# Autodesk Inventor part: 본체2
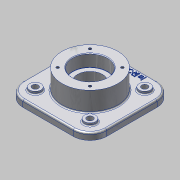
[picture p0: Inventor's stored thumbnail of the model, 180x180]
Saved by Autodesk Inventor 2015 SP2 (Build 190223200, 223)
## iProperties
Created: 2015-07
Part Number: 본체2
Material: 알루미늄 6061
Document SubType Name: Modeling
Designer: AMC
Density: 2.7 g/cm^3
Appearance: 알루미늄 - 평지
Mass: 1457.56 g
Surface Area: 803.25 cm^2
Volume: 539.836 cm^3
Author: AMC
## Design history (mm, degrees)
sketch "스케치1"
  geometry: L1 (-75, -75)-(75, -75); L2 (75, -75)-(75, 75); L3 (75, 75)-(-75, 75); L4 (-75, 75)-(-75, -75); L5 (-75, -75)-(75, 75); L6 (75, -75)-(-75, 75); 1 further point
  constraints: 12 end point, 2 midpoint, 2 parallel, 1 horizontal, 1 perpendicular
  dimensions: "d0" = 150 distance of L3.end L2.end; "d1" = 150 distance of L2.end L1.end
extrude "돌출1" new body sketch "스케치1" distance "d2" = 12; taper "d3" = 0 deg
sketch "스케치2"
  geometry: C1 r 50 at (0, 0); 1 further point
  constraints: 1 centre point, 1 coincident
  dimensions: "d4" = 100 diameter of C1
extrude "돌출2" join sketch "스케치2" stored distance "d5" = 70; taper "d6" = 0 deg
hole "구멍1" diameter "d9" = 45; stored, may be unused: countersink angle "d13" = 90 deg, drill point angle "d15" = 0 deg; dims "d10" = 6, "d11" = 62, "d12" = 22, "d14" = 35, "d132" = 10, "d133" = 10
hole "구멍2" diameter "d18" = 45; stored, may be unused: countersink angle "d22" = 90 deg, drill point angle "d24" = 0 deg; dims "d19" = 6, "d20" = 62, "d21" = 22, "d23" = 35, "d134" = 10, "d135" = 10
sketch "스케치3"
  geometry: L1 (0, 0)-(41, 0); L2 (0, 0)-(28.991, -28.991); A1 r 41 centre (0, 0) between (41, 0) and (28.991, -28.991); 1 further point
  constraints: 4 end point, 2 point on circle, 1 centre point, 1 coincident, 1 horizontal
  dimensions: "d25" = 82 diameter of A1; "d26" = 45 deg angle of L2 L1
hole "구멍3" sketch "스케치3" at (28.991, -28.991) diameter "d27" = 4.917; stored, may be unused: countersink angle "d31" = 90 deg, drill point angle "d33" = 118 deg; dims "d28" = 10, "d29" = 52, "d30" = 22, "d32" = 13
sketch "스케치4"
  geometry: L1 (0, 0)-(41, 0); L2 (0, 0)-(28.991, -28.991); A1 r 41 centre (0, 0) between (41, 0) and (28.991, -28.991); 1 further point
  constraints: 4 end point, 2 point on circle, 1 centre point, 1 coincident, 1 horizontal
  dimensions: "d37" = 82 diameter of A1; "d38" = 45 deg angle of L2 L1
hole "구멍4" sketch "스케치4" at (28.991, -28.991) diameter "d39" = 4.917; stored, may be unused: countersink angle "d43" = 90 deg, drill point angle "d45" = 118 deg; dims "d40" = 10, "d41" = 52, "d42" = 22, "d44" = 13
sketch "스케치6"
  geometry: L1 (75, 75)-(-75, 75) reference; L2 (-75, 75)-(-75, -75) reference; L3 (-75, -75)-(75, -75) reference; L4 (75, -75)-(75, 75) reference; C1 r 10 at (-49, 49); C2 r 10 at (49, 49); C3 r 10 at (49, -49); C4 r 10 at (-49, -49); 1 further point
  constraints: 4 centre point
  dimensions: "d72" = 20 diameter of C1; "d73" = 20 diameter of C2; "d74" = 20 diameter of C3; "d75" = 20 diameter of C4; "d76" = 26 distance from line of C1.centre L1; "d77" = 26 distance from line of L2 C1.centre; "d78" = 26 distance from line of C4.centre L2; "d79" = 26 distance from line of L3 C4.centre; "d80" = 26 distance from line of L4 C3.centre; "d81" = 26 distance from line of L3 C3.centre; "d82" = 26 distance from line of C2.centre L1; "d83" = 26 distance from line of C2.centre L4
extrude "돌출4" join sketch "스케치6" distance "d84" = 5; taper "d85" = 0 deg
hole "구멍6" diameter "d88" = 11; stored, may be unused: countersink angle "d92" = 90 deg, drill point angle "d94" = 0 deg; dims "d86" = 10, "d87" = 10, "d89" = 10, "d90" = 52, "d91" = 22, "d93" = 50
hole "구멍7" diameter "d97" = 11; stored, may be unused: countersink angle "d101" = 90 deg, drill point angle "d103" = 0 deg; dims "d95" = 10, "d96" = 10, "d98" = 10, "d99" = 52, "d100" = 22, "d102" = 50
hole "구멍8" diameter "d106" = 11; stored, may be unused: countersink angle "d110" = 90 deg, drill point angle "d112" = 0 deg; dims "d104" = 10, "d105" = 10, "d107" = 10, "d108" = 52, "d109" = 22, "d111" = 50
hole "구멍9" diameter "d115" = 11; stored, may be unused: countersink angle "d119" = 90 deg, drill point angle "d121" = 0 deg; dims "d113" = 10, "d114" = 10, "d116" = 10, "d117" = 52, "d118" = 22, "d120" = 50
fillet "모깎기1" dims "d122" = 2
fillet "모깎기2" dims "d123" = 30
fillet "모깎기4" dims "d125" = 0.3
chamfer "모따기1" distance "d126" = 1; stored, may be unused: second distance "d127" = 2, angle "d128" = 45 deg
sketch "스케치7"
  geometry: 2 further points
  constraints: 1 vertical alignment, 1 other
  dimensions: "d129" = 65 distance of point (0, 0) point (0, 65)
fillet "모깎기5" dims "d130" = 3
fillet "모깎기6" dims "d131" = 3
feature "엠보싱1" dims "d0" = 150, "d1" = 150, "d136" = 1, "d137" = 0
node "솔리드1"
pattern_circular "원형 패턴1" dims angle "d35" = 360 deg
pattern_circular "원형 패턴2" dims angle "d47" = 360 deg
